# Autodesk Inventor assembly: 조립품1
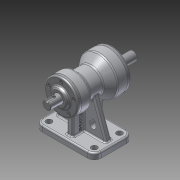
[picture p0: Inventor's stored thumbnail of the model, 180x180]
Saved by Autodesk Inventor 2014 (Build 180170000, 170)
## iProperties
Created: 2015-08
Part Number: 조립품1
Document SubType Name: Assembly
Designer: aapexcom
Author: aapexcom
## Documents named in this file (10)
- C:\Users\aapexcom\Desktop\450806V1003\조립품1.iam
- C:\Users\aapexcom\Desktop\450806V1003\본체.ipt
- C:\Users\aapexcom\Desktop\450806V1003\축.ipt
- C:\Users\aapexcom\Desktop\450806V1003\앞커버.ipt
- C:\Users\aapexcom\Desktop\450806V1003\뒤커버.ipt
- C:\Users\aapexcom\Desktop\450806V1003\베어링 6203.ipt
- C:\Users\aapexcom\Desktop\450806V1003\베어링 6205.ipt
- C:\Users\aapexcom\Desktop\450806V1003\오일실 .ipt
- 오일실 .ipt
- C:\Users\aapexcom\Desktop\450806V1003\M4x0.5.ipt
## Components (10 placed, 1 different names)
1. M4x0.5:1
2. M4x0.5:2
3. M4x0.5:3
4. M4x0.5:4
5. M4x0.5:5
6. M4x0.5:6
7. M4x0.5:7
8. M4x0.5:8
9. M4x0.5:9
10. M4x0.5:10
